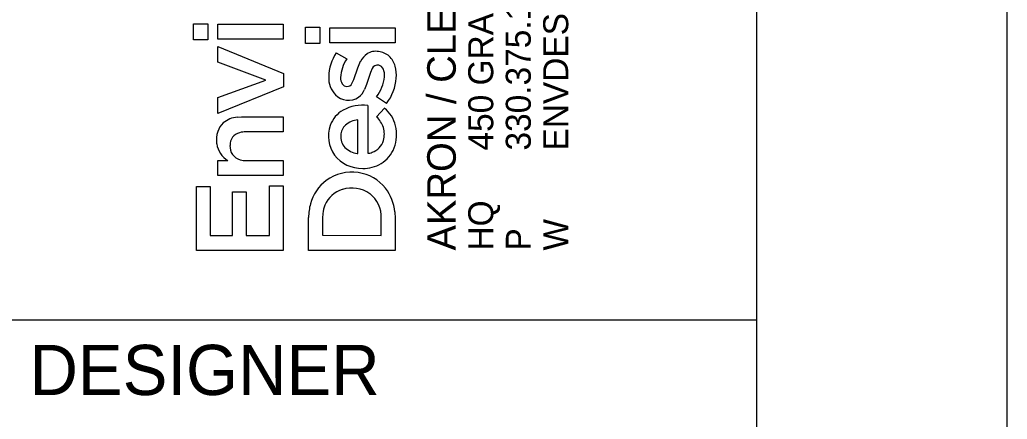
# Model space of a CAD drawing. Extents: x 0 to 34, y 0 to 22.
# Drawn here: x 32.03 to 34, y 2.302 to 3.098 of the extents above; entities that cross this region are included whole.
import ezdxf

# ---------------------------------------------------------------- set-up
doc = ezdxf.new("R2010")
doc.units = 0
for name, color, linetype in [('SH_Border', 7, 'Continuous'), ('SH_Cut_Line', 7, 'Continuous'), ('SH_Data', 7, 'Continuous'), ('SH_Text', 7, 'Continuous')]:
    doc.layers.add(name, color=color, linetype=linetype)

msp = doc.modelspace()

# ---------------------------------------------------------------- linework, layer by layer
at = {"layer": 'SH_Border'}
msp.add_line((32, 2.5), (33.5, 2.5), dxfattribs=at)
msp.add_lwpolyline([(1.5, 21.5), (33.5, 21.5), (33.5, 0.5), (1.5, 0.5)], close=True, dxfattribs=at)
at = {"layer": 'SH_Cut_Line'}
msp.add_lwpolyline([(0, 0), (34, 0), (34, 22), (0, 22)], close=True, dxfattribs=at)
at = {"layer": 'SH_Text'}
for p, q in [((32.3771, 3.0582), (32.3771, 3.0903)), ((32.3771, 3.0903), (32.4054, 3.0903)), ((32.4054, 3.0903), (32.4054, 3.0582)), ((32.4254, 3.0594), (32.4254, 3.0893)), ((32.4254, 3.0893), (32.5557, 3.0893)), ((32.5557, 3.0893), (32.5557, 3.0594)), ((32.6005, 3.0511), (32.6005, 3.0832)), ((32.6005, 3.0832), (32.6289, 3.0832)), ((32.6289, 3.0832), (32.6289, 3.0511)), ((32.6489, 3.0523), (32.6489, 3.0822)), ((32.6489, 3.0822), (32.7792, 3.0822)), ((32.7792, 3.0822), (32.7792, 3.0523)), ((32.4054, 3.0582), (32.3771, 3.0582)), ((32.5557, 3.0594), (32.4254, 3.0594)), ((32.4254, 3.0133), (32.4254, 3.0446)), ((32.4254, 3.0446), (32.5567, 2.9913)), ((32.6289, 3.0511), (32.6005, 3.0511)), ((32.7792, 3.0523), (32.6489, 3.0523)), ((32.6615, 3.0321), (32.6827, 3.0203)), ((32.7048, 3.0026), (32.7104, 3.0153)), ((32.5212, 2.978), (32.4254, 3.0133)), ((32.6967, 2.9787), (32.7048, 3.0026)), ((32.7334, 3.001), (32.7298, 2.9933)), ((32.4254, 2.9429), (32.5212, 2.978)), ((32.5567, 2.9913), (32.5567, 2.9644)), ((32.693, 2.9712), (32.6967, 2.9787)), ((32.7298, 2.9933), (32.7221, 2.9688)), ((32.5567, 2.9644), (32.4254, 2.9109)), ((32.7221, 2.9688), (32.7182, 2.9592)), ((32.4254, 2.9109), (32.4254, 2.9429)), ((32.7621, 2.9314), (32.742, 2.9447)), ((32.7245, 2.9275), (32.7246, 2.8319)), ((32.7423, 2.9046), (32.7577, 2.922)), ((32.4644, 2.904), (32.4729, 2.9044)), ((32.4729, 2.9044), (32.5557, 2.9044)), ((32.5557, 2.9044), (32.5557, 2.8746)), ((32.7049, 2.8318), (32.7049, 2.8983)), ((32.5557, 2.8746), (32.4814, 2.8746)), ((32.4254, 2.7875), (32.4254, 2.8173)), ((32.4254, 2.8173), (32.4455, 2.8173)), ((32.4822, 2.8173), (32.5557, 2.8173)), ((32.5557, 2.8173), (32.5557, 2.7876)), ((32.7036, 2.8317), (32.7049, 2.8318)), ((32.5557, 2.7876), (32.4254, 2.7875)), ((32.383, 2.6379), (32.383, 2.766)), ((32.383, 2.766), (32.4101, 2.766)), ((32.4101, 2.766), (32.4101, 2.6683)), ((32.5286, 2.6683), (32.5286, 2.7672)), ((32.5286, 2.7672), (32.5557, 2.7672)), ((32.5557, 2.7672), (32.5557, 2.6379)), ((32.455, 2.6683), (32.455, 2.7549)), ((32.455, 2.7549), (32.4822, 2.7549)), ((32.4822, 2.7549), (32.4822, 2.6683)), ((32.6064, 2.638), (32.6064, 2.704)), ((32.6347, 2.7118), (32.6341, 2.7023)), ((32.6341, 2.7023), (32.6341, 2.6684)), ((32.7515, 2.6683), (32.7515, 2.7024)), ((32.7785, 2.715), (32.7792, 2.7021)), ((32.7792, 2.7021), (32.7792, 2.638)), ((32.4101, 2.6683), (32.455, 2.6683)), ((32.4822, 2.6683), (32.5286, 2.6683)), ((32.6341, 2.6684), (32.7515, 2.6683)), ((32.5557, 2.6379), (32.383, 2.6379)), ((32.7792, 2.638), (32.6064, 2.638))]:
    msp.add_line(p, q, dxfattribs=at)
for points in [[(32.3771, 3.0582), (32.3771, 3.0903), (32.4054, 3.0903), (32.4054, 3.0582)], [(32.4254, 3.0594), (32.4254, 3.0893), (32.5557, 3.0893), (32.5557, 3.0594)], [(32.6005, 3.0511), (32.6005, 3.0832), (32.6289, 3.0832), (32.6289, 3.0511)], [(32.6489, 3.0523), (32.6489, 3.0822), (32.7792, 3.0822), (32.7792, 3.0523)], [(32.4254, 2.9109), (32.4254, 2.9429), (32.5212, 2.978), (32.4254, 3.0133), (32.4254, 3.0446), (32.5567, 2.9913), (32.5567, 2.9644)], [(32.383, 2.6379), (32.383, 2.766), (32.4101, 2.766), (32.4101, 2.6683), (32.455, 2.6683), (32.455, 2.7549), (32.4822, 2.7549), (32.4822, 2.6683), (32.5286, 2.6683), (32.5286, 2.7672), (32.5557, 2.7672), (32.5557, 2.6379)]]:
    msp.add_lwpolyline(points, close=True, dxfattribs=at)
for points in [[(32.6615, 3.0321), (32.6827, 3.0203)], [(32.693, 2.9712), (32.6967, 2.9787), (32.7048, 3.0026), (32.7104, 3.0153)], [(32.7334, 3.001), (32.7298, 2.9933), (32.7221, 2.9688), (32.7182, 2.9592)], [(32.7621, 2.9314), (32.742, 2.9447)], [(32.7245, 2.9275), (32.7246, 2.8319)], [(32.7423, 2.9046), (32.7577, 2.922)], [(32.4644, 2.904), (32.4729, 2.9044), (32.5557, 2.9044), (32.5557, 2.8746), (32.4814, 2.8746)], [(32.7036, 2.8317), (32.7049, 2.8318), (32.7049, 2.8983)], [(32.4254, 2.7875), (32.4254, 2.8173), (32.4455, 2.8173)], [(32.4822, 2.8173), (32.5557, 2.8173), (32.5557, 2.7876), (32.4254, 2.7875)], [(32.7785, 2.715), (32.7792, 2.7021), (32.7792, 2.638), (32.6064, 2.638)], [(32.6064, 2.638), (32.6064, 2.704)], [(32.6347, 2.7118), (32.6341, 2.7023), (32.6341, 2.6684), (32.7515, 2.6683), (32.7515, 2.7024)]]:
    msp.add_lwpolyline(points, dxfattribs=at)
for centre, radius, start, end in [((32.7406, 3.0026), 0.0326, 80.1719, 122.5197), ((32.7406, 3.0026), 0.0326, 80.1719, 122.5197), ((32.7428, 2.9982), 0.0367, 47.7934, 84.6892), ((32.7428, 2.9982), 0.0367, 47.7934, 84.6892), ((32.7364, 2.9826), 0.0897, 146.531, 178.7571), ((32.7364, 2.9826), 0.0897, 146.531, 178.7571), ((32.7452, 2.9789), 0.0749, 146.5112, 176.9101), ((32.7452, 2.9789), 0.0749, 146.5112, 176.9101), ((32.7466, 2.9971), 0.0405, 125.5118, 153.4159), ((32.7466, 2.9971), 0.0405, 125.5118, 153.4159), ((32.7379, 2.9946), 0.0427, 14.9966, 46.2063), ((32.7379, 2.9946), 0.0427, 14.9966, 46.2063), ((32.7438, 2.9963), 0.0114, 76.6609, 155.7053), ((32.7438, 2.9963), 0.0114, 76.6609, 155.7053), ((32.744, 2.9951), 0.0126, 21.5098, 78.5262), ((32.744, 2.9951), 0.0126, 21.5098, 78.5262), ((32.7259, 2.9877), 0.0321, 354.5726, 22.068), ((32.7259, 2.9877), 0.0321, 354.5726, 22.068), ((32.7104, 2.9867), 0.0712, 355.8306, 15.3914), ((32.7104, 2.9867), 0.0712, 355.8306, 15.3914), ((32.6967, 2.9824), 0.0501, 177.5366, 222.7932), ((32.6967, 2.9824), 0.0501, 177.5366, 222.7932), ((32.6931, 2.9823), 0.0228, 178.4747, 211.0868), ((32.6931, 2.9823), 0.0228, 178.4747, 211.0868), ((32.6825, 2.9915), 0.0757, 321.811, 354.7969), ((32.6825, 2.9915), 0.0757, 321.811, 354.7969), ((32.6895, 2.9882), 0.0922, 321.9777, 355.8738), ((32.6895, 2.9882), 0.0922, 321.9777, 355.8738), ((32.6833, 2.9767), 0.0115, 212.2368, 268.3777), ((32.6833, 2.9767), 0.0115, 212.2368, 268.3777), ((32.6834, 2.9759), 0.0107, 267.716, 333.7337), ((32.6834, 2.9759), 0.0107, 267.716, 333.7337), ((32.681, 2.9758), 0.0408, 308.0877, 335.9874), ((32.681, 2.9758), 0.0408, 308.0877, 335.9874), ((32.686, 2.9753), 0.0375, 225.9854, 302.4797), ((32.686, 2.9753), 0.0375, 225.9854, 302.4797), ((32.7024, 2.8691), 0.0558, 118.8308, 160.6244), ((32.7024, 2.8691), 0.0558, 118.8308, 160.6244), ((32.7152, 2.8441), 0.0838, 83.615, 118.2876), ((32.7152, 2.8441), 0.0838, 83.615, 118.2876), ((32.7174, 2.8717), 0.0644, 13.5336, 51.3615), ((32.7174, 2.8717), 0.0644, 13.5336, 51.3615), ((32.4687, 2.8543), 0.0499, 94.9696, 130.2225), ((32.4687, 2.8543), 0.0499, 94.9696, 130.2225), ((32.7079, 2.8561), 0.0424, 94.008, 130.8817), ((32.7079, 2.8561), 0.0424, 94.008, 130.8817), ((32.7038, 2.8656), 0.0549, 19.0357, 45.4406), ((32.7038, 2.8656), 0.0549, 19.0357, 45.4406), ((32.4635, 2.8626), 0.0402, 132.2219, 161.6818), ((32.4635, 2.8626), 0.0402, 132.2219, 161.6818), ((32.7104, 2.8661), 0.0644, 160.5201, 215.7831), ((32.7104, 2.8661), 0.0644, 160.5201, 215.7831), ((32.7005, 2.8663), 0.0298, 132.9851, 177.179), ((32.7005, 2.8663), 0.0298, 132.9851, 177.179), ((32.7107, 2.8697), 0.047, 344.6059, 17.007), ((32.7107, 2.8697), 0.047, 344.6059, 17.007), ((32.7064, 2.8692), 0.0758, 339.3542, 13.3785), ((32.7064, 2.8692), 0.0758, 339.3542, 13.3785), ((32.4787, 2.8582), 0.056, 162.2736, 187.7919), ((32.4787, 2.8582), 0.056, 162.2736, 187.7919), ((32.4748, 2.8487), 0.025, 103.6865, 182.2187), ((32.4748, 2.8487), 0.025, 103.6865, 182.2187), ((32.4811, 2.8286), 0.046, 89.6049, 105.3284), ((32.4811, 2.8286), 0.046, 89.6049, 105.3284), ((32.7017, 2.865), 0.0311, 175.0013, 223.283), ((32.7017, 2.865), 0.0311, 175.0013, 223.283), ((32.7224, 2.8671), 0.035, 288.0077, 343.5508), ((32.7224, 2.8671), 0.035, 288.0077, 343.5508), ((32.4703, 2.858), 0.0476, 188.962, 238.7037), ((32.4703, 2.858), 0.0476, 188.962, 238.7037), ((32.4773, 2.8456), 0.0276, 175.5854, 255.1439), ((32.4773, 2.8456), 0.0276, 175.5854, 255.1439), ((32.7089, 2.8736), 0.0423, 225.0619, 262.7974), ((32.7089, 2.8736), 0.0423, 225.0619, 262.7974), ((32.7189, 2.8652), 0.0626, 300.9427, 338.7323), ((32.7189, 2.8652), 0.0626, 300.9427, 338.7323), ((32.4818, 2.8595), 0.0422, 254.0916, 270.5284), ((32.4818, 2.8595), 0.0422, 254.0916, 270.5284), ((32.7125, 2.8705), 0.0687, 217.7452, 271.6543), ((32.7125, 2.8705), 0.0687, 217.7452, 271.6543), ((32.7247, 2.8522), 0.0202, 269.7003, 294.8711), ((32.7247, 2.8522), 0.0202, 269.7003, 294.8711), ((32.7155, 2.8724), 0.0706, 269.2048, 300.3341), ((32.7155, 2.8724), 0.0706, 269.2048, 300.3341), ((32.6939, 2.7089), 0.0865, 127.2362, 165.148), ((32.6939, 2.7089), 0.0865, 127.2362, 165.148), ((32.6923, 2.7079), 0.0864, 81.194, 125.9984), ((32.6923, 2.7079), 0.0864, 81.194, 125.9984), ((32.6946, 2.7113), 0.0827, 37.8521, 82.402), ((32.6946, 2.7113), 0.0827, 37.8521, 82.402), ((32.6889, 2.7078), 0.054, 106.1881, 157.3861), ((32.6889, 2.7078), 0.054, 106.1881, 157.3861), ((32.6928, 2.6986), 0.0639, 55.6727, 107.2093), ((32.6928, 2.6986), 0.0639, 55.6727, 107.2093), ((32.6859, 2.7057), 0.0931, 5.7333, 37.304), ((32.6859, 2.7057), 0.0931, 5.7333, 37.304), ((32.6929, 2.705), 0.0587, 357.4662, 52.2665), ((32.6929, 2.705), 0.0587, 357.4662, 52.2665), ((32.7143, 2.7028), 0.1078, 164.7861, 179.3704), ((32.7143, 2.7028), 0.1078, 164.7861, 179.3704), ((32.6983, 2.7039), 0.0641, 157.3571, 172.9275), ((32.6983, 2.7039), 0.0641, 157.3571, 172.9275)]:
    msp.add_arc(centre, radius, start, end, dxfattribs=at)

# ---------------------------------------------------------------- texts
at = {"layer": 'SH_Data'}
msp.add_text('DESIGNER', height=0.1, dxfattribs=at).set_placement((32.05, 2.35))
at = {"layer": 'SH_Text'}
for s, height, p in [('450 GRANT ST., AKRON, OH  44311', 0.049846, (32.9749, 2.8374)), ('AKRON / CLEVELAND / COLUMBUS', 0.056969, (32.9001, 2.638)), ('ENVDESIGNGROUP.COM', 0.049846, (33.1244, 2.8374)), ('330.375.1390', 0.049846, (33.0497, 2.8374)), ('HQ ', 0.04985, (32.9749, 2.638)), ('W', 0.0498, (33.1244, 2.638)), ('P', 0.0498, (33.0497, 2.638))]:
    msp.add_text(s, height=height, rotation=90, dxfattribs=at).set_placement(p)

doc.saveas('drawing.dxf')
